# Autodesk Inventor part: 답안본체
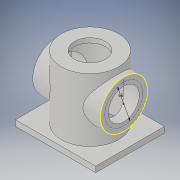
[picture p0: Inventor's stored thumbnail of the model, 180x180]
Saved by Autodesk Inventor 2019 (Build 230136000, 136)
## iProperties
Created: 2020-12
Part Number: 답안본체
Material: 일반
Document SubType Name: Modeling
Designer: jun-1-10
Density: 1 g/cm^3
Appearance: 기본값
Author: jun-1-10
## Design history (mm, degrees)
sketch "스케치1"
  geometry: L1 (70, 60)-(-70, 60); L2 (-70, 60)-(-70, -60); L3 (-70, -60)-(70, -60); L4 (70, -60)-(70, 60); L5 (70, 60)-(-70, -60); L6 (-70, 60)-(70, -60); 1 further point
  constraints: 12 end point, 2 midpoint, 2 parallel, 1 horizontal, 1 perpendicular
  dimensions: "d0" = 140 distance of L3.end L2.end; "d1" = 120 distance of L2.end L1.end
extrude "돌출1" new body sketch "스케치1" distance "d2" = 10; taper "d3" = 0 deg
sketch "스케치2"
  geometry: C1 r 50 at (0, 0); 1 further point
  constraints: 1 centre point, 1 coincident
  dimensions: "d4" = 100 diameter of C1
extrude "돌출2" join sketch "스케치2" distance "d5" = 110; taper "d6" = 0 deg
sketch "스케치3"
  geometry: C1 r 50 at (0, 0) reference; 2 further points
  constraints: 1 coincident
hole "구멍1" sketch "스케치3" at (0, 0) diameter "d7" = 54; stored, may be unused: countersink angle "d11" = 90 deg, drill point angle "d13" = 118 deg; dims "d8" = 6, "d9" = 84, "d10" = 112, "d12" = 8
node "작업 평면2"
sketch "스케치5"
  geometry: L1 (0, 60)-(0, -60) reference; C1 r 41 at (68.419, 0); 2 further points
  constraints: 1 centre point, 1 horizontal alignment, 1 midpoint
  dimensions: "d15" = 82 diameter of C1
extrude "돌출3" join sketch "스케치5" stored distance "d16" = 110; taper "d17" = 0 deg
sketch "스케치6"
  geometry: C1 r 41 at (0, 0) reference; 2 further points
  constraints: 1 coincident
hole "구멍2" sketch "스케치6" at (0, 0) diameter "d18" = 54; stored, may be unused: countersink angle "d22" = 90 deg, drill point angle "d24" = 118 deg; dims "d19" = 6, "d20" = 84, "d21" = 112, "d23" = 8
sketch "스케치7" dims "d25" = 66
  geometry: C1 r 41 at (0, 0) reference; 3 further points
  constraints: 2 vertical alignment, 1 coincident, 2 other
node "솔리드1"
mirror "미러1"
other parameters: "d14" = 59
